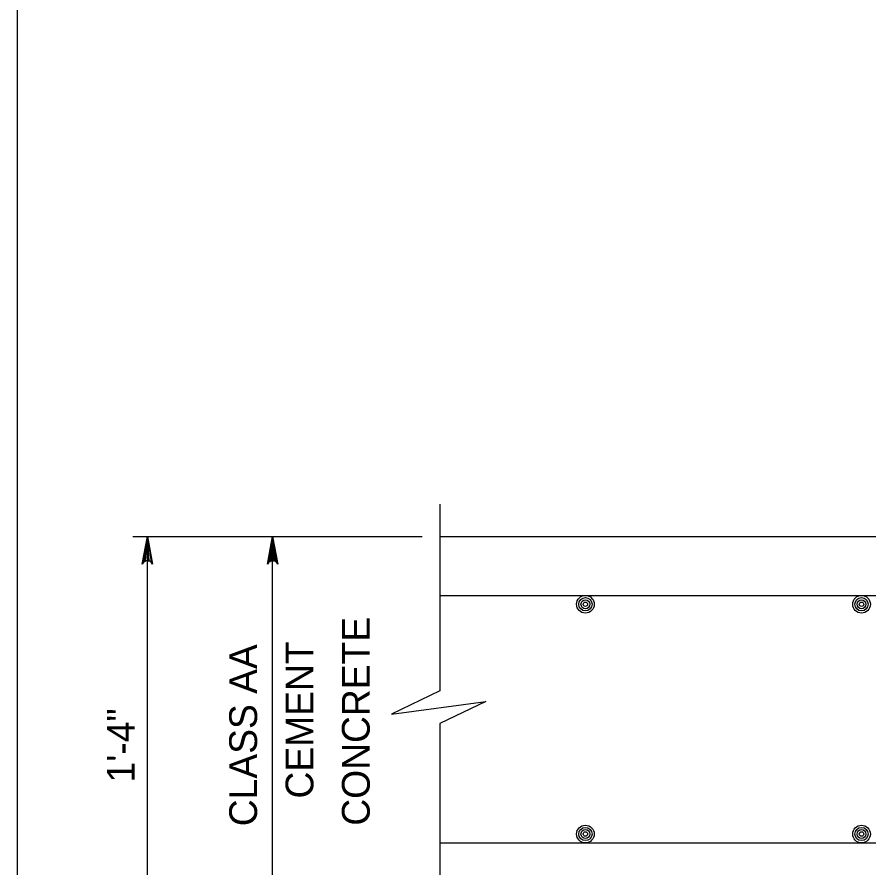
# Model space of a CAD drawing. Extents: x 638079 to 640019, y 297691 to 298879.
# Drawn here: x 639154 to 639245.9, y 298541.4 to 298633.1 of the extents above; entities that cross this region are included whole.
import ezdxf

# ---------------------------------------------------------------- set-up
doc = ezdxf.new("R2010")
doc.units = 0
doc.layers.add('1', color=7, linetype='Continuous')

msp = doc.modelspace()

# ---------------------------------------------------------------- linework, layer by layer
at = {"layer": '1'}
for p, q in [((639199.598, 298580.621), (639199.598, 298560.498)), ((639166.511, 298577.121), (639197.7, 298577.121)), ((639168.08, 298506.002), (639168.08, 298577.121)), ((639181.579, 298536.482), (639181.579, 298577.121)), ((639199.598, 298577.121), (639341.94, 298577.121)), ((639199.598, 298570.772), (639249.233, 298570.772)), ((639199.598, 298556.98), (639199.598, 298511.569)), ((639199.598, 298544.103), (639249.233, 298544.103))]:
    msp.add_line(p, q, dxfattribs=at)
for points in [[(639940.033, 298300.226), (639940.033, 298864.226), (639154.033, 298864.226), (639154.033, 298300.226), (639940.033, 298300.226), (639940.033, 298326.585), (639740.033, 298326.585), (639740.033, 298391.263), (639940.033, 298391.263), (639940.033, 298420.226), (639740.033, 298420.226), (639740.033, 298300.226), (639818.835, 298300.226), (639818.835, 298326.585), (639818.835, 298300.226), (639895.835, 298300.226), (639895.835, 298326.585), (639895.835, 298314.269), (639940.033, 298314.269)], [(639168.08, 298577.121), (639168.64, 298574.139), (639168.48, 298574.368), (639168.28, 298574.487), (639168.08, 298574.521), (639167.88, 298574.487), (639167.68, 298574.368), (639167.521, 298574.139), (639168.08, 298577.121), (639167.68, 298574.368), (639167.88, 298574.487), (639168.08, 298577.121), (639168.08, 298574.521), (639168.28, 298574.487), (639168.08, 298577.121), (639168.48, 298574.368)], [(639181.579, 298577.121), (639182.139, 298574.139), (639182.059, 298574.254), (639181.979, 298574.368), (639181.879, 298574.428), (639181.779, 298574.487), (639181.679, 298574.504), (639181.579, 298574.521), (639181.479, 298574.504), (639181.379, 298574.487), (639181.279, 298574.428), (639181.179, 298574.368), (639181.1, 298574.254), (639181.02, 298574.139), (639181.579, 298577.121), (639181.1, 298574.254), (639181.179, 298574.368), (639181.579, 298577.121), (639181.279, 298574.428), (639181.379, 298574.487), (639181.579, 298577.121), (639181.479, 298574.504), (639181.579, 298574.521), (639181.579, 298577.121), (639181.679, 298574.504), (639181.779, 298574.487), (639181.579, 298577.121), (639181.879, 298574.428), (639181.979, 298574.368), (639181.579, 298577.121), (639182.059, 298574.254)], [(639199.598, 298560.498), (639194.413, 298557.961), (639204.561, 298559.341), (639199.598, 298556.98)]]:
    msp.add_lwpolyline(points, dxfattribs=at)
for centre, radius in [((639215.3, 298569.821), 0.952), ((639245.064, 298569.821), 0.952), ((639215.3, 298569.821), 0.714), ((639215.3, 298569.821), 0.476), ((639215.3, 298569.821), 0.238), ((639245.064, 298569.821), 0.714), ((639245.064, 298569.821), 0.476), ((639245.064, 298569.821), 0.238), ((639215.3, 298545.053), 0.952), ((639245.064, 298545.053), 0.952), ((639215.3, 298545.053), 0.714), ((639215.3, 298545.053), 0.476), ((639215.3, 298545.053), 0.238), ((639245.064, 298545.053), 0.714), ((639245.064, 298545.053), 0.476), ((639245.064, 298545.053), 0.238)]:
    msp.add_circle(centre, radius, dxfattribs=at)

# ---------------------------------------------------------------- texts
for s, p in [('CONCRETE', (639192.053, 298545.952)), ('CLASS AA', (639179.909, 298545.893)), ('CEMENT', (639185.981, 298548.882)), ('1\'-4"', (639166.729, 298550.615))]:
    msp.add_text(s, height=3, rotation=90, dxfattribs=at).set_placement(p)

doc.saveas('drawing.dxf')
